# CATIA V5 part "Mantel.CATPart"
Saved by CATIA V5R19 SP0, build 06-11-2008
Part number: mantel
Bounding box of the stored display mesh (mm): x 0 to 30, y -50 to 50, z -50 to 50
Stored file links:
  H:\Bachelorarbeit_Hahn\Neue Vereinfachung\Mantel.CATPart
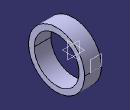
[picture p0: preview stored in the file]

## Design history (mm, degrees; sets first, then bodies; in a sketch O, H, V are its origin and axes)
Body1 (main body)
  Sketch1 on yz-plane, origin (0, 0, 0), H (0, 1, 0), V (0, 0, 1)
    circle A1 centre (0, 0) radius 40
    circle A2 centre (0, 0) radius 50
    radius A1 = 40
    radius A2 = 50
  Pad1: profile Sketch1, direction (1, 0, 0), length 30
  Plane1: type Offset, Offset 40, RefPlane zx-plane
